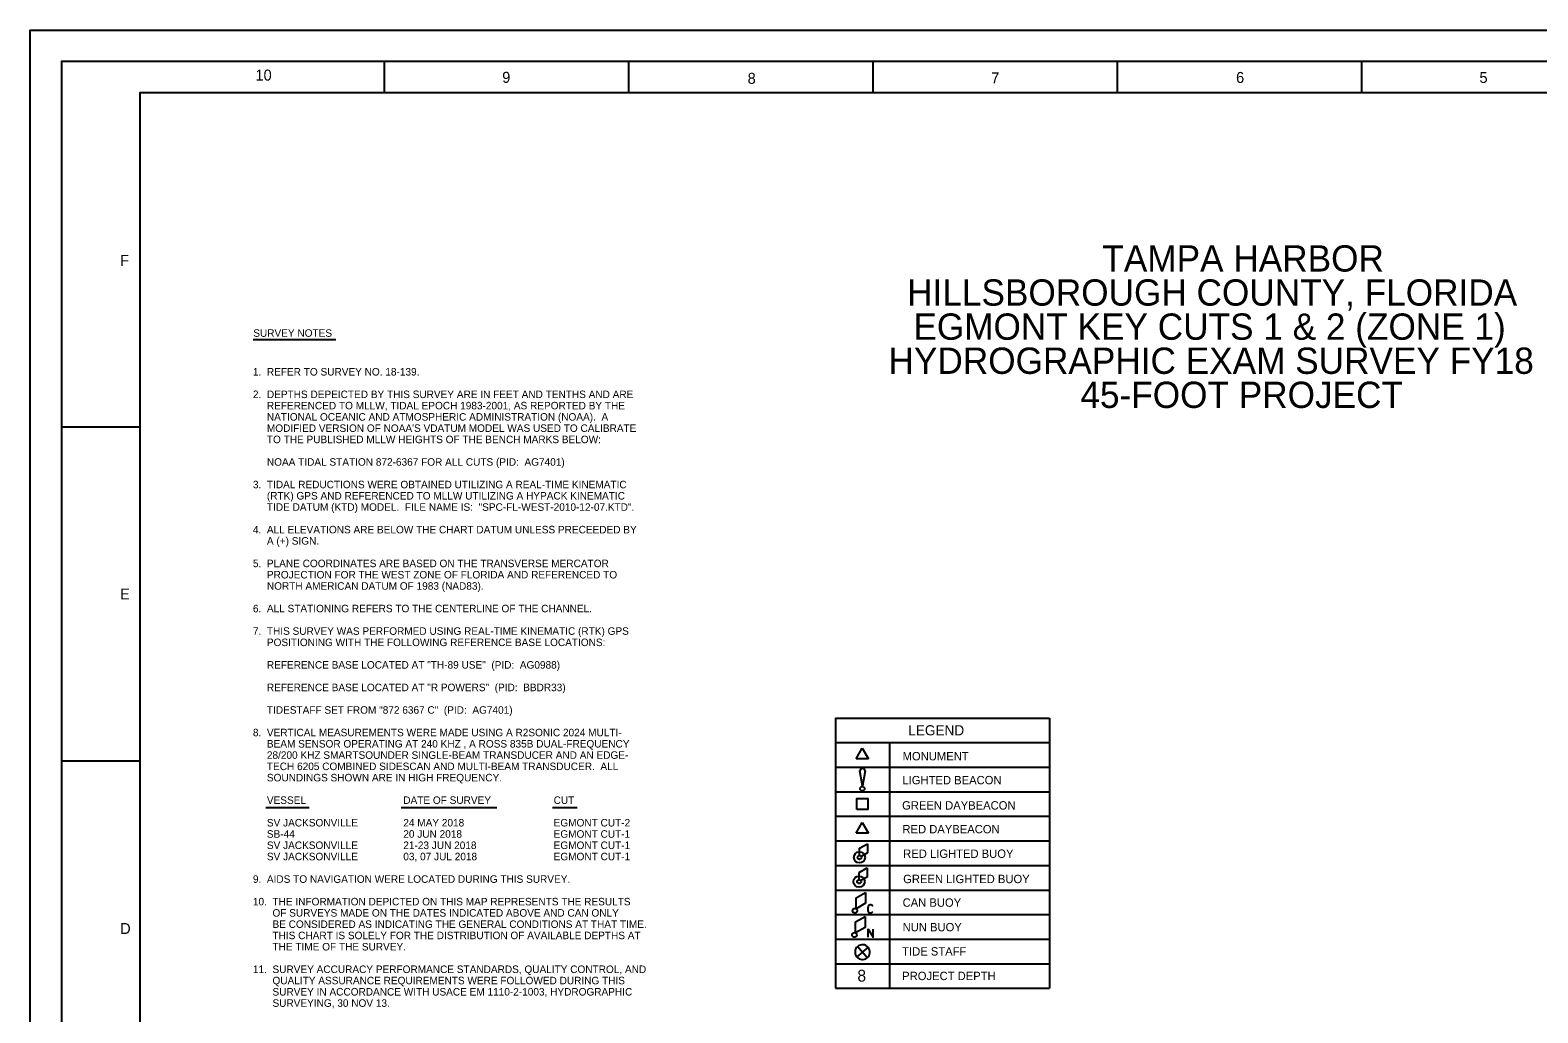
# Model space of a CAD drawing. Extents: x 315926 to 491925, y 1158891 to 1294891.
# Drawn here: x 315926 to 412183, y 1232125 to 1294891 of the extents above; entities that cross this region are included whole.
import ezdxf

# ---------------------------------------------------------------- set-up
doc = ezdxf.new("R2010")
doc.units = 0
for name, color, linetype in [('G-ANNO-NPLT', 7, 'Continuous'), ('G-ANNO-TTLB', 7, 'Continuous'), ('V-ANNO-LEGN', 7, 'Continuous'), ('V-ANNO-TEXT', 7, 'Continuous')]:
    doc.layers.add(name, color=color, linetype=linetype)

msp = doc.modelspace()

# ---------------------------------------------------------------- linework, layer by layer
at = {"layer": 'G-ANNO-NPLT'}
msp.add_lwpolyline([(315926, 1294891), (491925, 1294891), (491925, 1158891), (315926, 1158891)], close=True, dxfattribs=at)
msp.add_lwpolyline([(315926, 1292891), (315926, 1294891), (317926, 1294891)], dxfattribs=at)
at = {"layer": 'G-ANNO-TTLB'}
for p, q in [((338526, 1292891), (338526, 1290891)), ((354126, 1292891), (354126, 1290891)), ((354126, 1292891), (354126, 1290891)), ((369726, 1292891), (369726, 1290891)), ((385326, 1292891), (385326, 1290891)), ((400926, 1292891), (400926, 1290891)), ((317926, 1269551), (322926, 1269551)), ((317926, 1248219), (322926, 1248219))]:
    msp.add_line(p, q, dxfattribs=at)
for points in [[(317926, 1160891), (489925, 1160891), (489925, 1292891), (317926, 1292891)], [(487925, 1290891), (322926, 1290891), (322926, 1162891), (487925, 1162891)]]:
    msp.add_lwpolyline(points, close=True, dxfattribs=at)
at = {"layer": 'V-ANNO-LEGN'}
for p, q in [((367333, 1250952), (367333, 1233696)), ((367333, 1250952), (380999, 1250952)), ((380999, 1250952), (380999, 1233696)), ((367333, 1249383), (380999, 1249383)), ((368655, 1248353), (369055, 1249039)), ((369055, 1249039), (369447, 1248354)), ((370793, 1249376), (370793, 1233696)), ((367333, 1247815), (380999, 1247815)), ((369449, 1248350), (368655, 1248353)), ((369059, 1246625), (368892, 1247574)), ((369226, 1247574), (369059, 1246625)), ((367333, 1246247), (380999, 1246247)), ((367333, 1244678), (380999, 1244678)), ((368655, 1243606), (369055, 1244293)), ((369055, 1244293), (369447, 1243608)), ((367333, 1243109), (380999, 1243109)), ((369449, 1243604), (368655, 1243606)), ((368874, 1242636), (369380, 1242928)), ((369380, 1242928), (369380, 1242344)), ((368874, 1242177), (368874, 1242636)), ((369380, 1242344), (368982, 1242114)), ((367333, 1241540), (380999, 1241540)), ((368850, 1241093), (369356, 1241385)), ((368850, 1240634), (368850, 1241093)), ((369356, 1240801), (368958, 1240571)), ((369356, 1241385), (369356, 1240801)), ((367333, 1239971), (380999, 1239971)), ((368656, 1239473), (369257, 1239821)), ((369257, 1239821), (369258, 1239126)), ((368657, 1238777), (368656, 1239473)), ((369258, 1239126), (368657, 1238777)), ((367333, 1238402), (380999, 1238402)), ((368624, 1237235), (368627, 1237930)), ((368627, 1237930), (369230, 1238275)), ((369230, 1238275), (369228, 1237580)), ((369228, 1237580), (368624, 1237235)), ((367333, 1236834), (380999, 1236834)), ((369062, 1236003), (368697, 1235700)), ((368759, 1236369), (369062, 1236003)), ((369062, 1236003), (369428, 1236307)), ((369366, 1235638), (369062, 1236003)), ((367333, 1235265), (380999, 1235265)), ((367333, 1233696), (380999, 1233696))]:
    msp.add_line(p, q, dxfattribs=at)
msp.add_lwpolyline([(368703, 1245111), (368704, 1245819), (369412, 1245818), (369411, 1245110)], close=True, dxfattribs=at)
for points in [[(369720, 1238916), (369656, 1239000), (369592, 1239016), (369548, 1239016), (369488, 1238999), (369420, 1238916), (369405, 1238804), (369405, 1238744), (369405, 1238704), (369409, 1238668), (369421, 1238604), (369489, 1238524), (369549, 1238509), (369585, 1238509), (369653, 1238525), (369720, 1238605)], [(369431, 1236958), (369433, 1237465), (369746, 1236957), (369749, 1237464)]]:
    msp.add_lwpolyline(points, dxfattribs=at)
for centre, radius in [((369057, 1246444), 143), ((368874, 1242052), 355), ((368874, 1242052), 125), ((368850, 1240509), 355), ((368850, 1240509), 125), ((368585, 1238647), 149), ((368552, 1237104), 149)]:
    msp.add_circle(centre, radius, dxfattribs=at)
for centre, radius, start, end in [((369059, 1247561), 168, 4.64421, 175.35452), ((369062, 1236004), 475, 129.68581, 219.68582), ((369062, 1236004), 475, 39.68564, 129.68577), ((369062, 1236004), 475, 309.6858, 39.68585), ((369062, 1236004), 475, 219.6858, 309.68579)]:
    msp.add_arc(centre, radius, start, end, dxfattribs=at)
at = {"layer": 'V-ANNO-TEXT'}
for p, q in [((330171, 1275132), (335438, 1275132)), ((330981, 1245243), (333745, 1245243)), ((339606, 1245243), (345719, 1245243)), ((349268, 1245243), (350843, 1245243))]:
    msp.add_line(p, q, dxfattribs=at)

# ---------------------------------------------------------------- texts
at = {"layer": 'G-ANNO-TTLB'}
for s, p in [('10', (330309, 1291669)), ('9', (346061, 1291528)), ('8', (361731, 1291462)), ('7', (377279, 1291491)), ('6', (392917, 1291519)), ('5', (408456, 1291518)), ('F', (321668, 1279836)), ('E', (321663, 1258528)), ('D', (321668, 1237161))]:
    msp.add_text(s, height=700, dxfattribs=at).set_placement(p)
at = {"layer": 'V-ANNO-LEGN'}
for s, height, p in [('LEGEND', 649, (371989, 1249849)), ('MONUMENT', 535.4, (371627, 1248251)), ('LIGHTED BEACON', 535.39, (371616, 1246722)), ('GREEN DAYBEACON', 535.39, (371596, 1245108)), ('RED DAYBEACON', 535.39, (371616, 1243590)), ('RED LIGHTED BUOY', 535.39, (371664, 1242023)), ('GREEN LIGHTED BUOY', 535.39, (371664, 1240410)), ('CAN BUOY', 535.4, (371627, 1238902)), ('NUN BUOY', 535.4, (371627, 1237333)), ('TIDE STAFF', 535.4, (371600, 1235783)), ('8', 751, (368738, 1234123)), ('PROJECT DEPTH', 535.39, (371600, 1234217))]:
    msp.add_text(s, height=height, rotation=360, dxfattribs=at).set_placement(p)
at = {"layer": 'V-ANNO-TEXT'}
for s, height, p in [('TAMPA HARBOR', 1680, (384379, 1279471)), ('HILLSBOROUGH COUNTY, FLORIDA', 1680, (371917, 1277293)), ('EGMONT KEY CUTS 1 & 2 (ZONE 1)', 1680, (372312, 1275115)), ('SURVEY NOTES', 480, (330171, 1275305)), ('HYDROGRAPHIC EXAM SURVEY FY18', 1680, (370728, 1272937)), ('1.  REFER TO SURVEY NO. 18-139.  ', 480, (330149, 1272830)), ('2.  DEPTHS DEPEICTED BY THIS SURVEY ARE IN FEET AND TENTHS AND ARE', 480, (330149, 1271390)), ('45-FOOT PROJECT', 1680, (382976, 1270759)), ('     REFERENCED TO MLLW, TIDAL EPOCH 1983-2001, AS REPORTED BY THE', 480, (330149, 1270670)), ('     NATIONAL OCEANIC AND ATMOSPHERIC ADMINISTRATION (NOAA).  A', 480, (330149, 1269950)), ("     MODIFIED VERSION OF NOAA'S VDATUM MODEL WAS USED TO CALIBRATE", 480, (330149, 1269230)), ('     TO THE PUBLISHED MLLW HEIGHTS OF THE BENCH MARKS BELOW:', 480, (330149, 1268510)), ('     NOAA TIDAL STATION 872-6367 FOR ALL CUTS (PID:  AG7401)', 480, (330149, 1267070)), ('3.  TIDAL REDUCTIONS WERE OBTAINED UTILIZING A REAL-TIME KINEMATIC', 480, (330149, 1265630)), ('     (RTK) GPS AND REFERENCED TO MLLW UTILIZING A HYPACK KINEMATIC', 480, (330149, 1264910)), ('     TIDE DATUM (KTD) MODEL.  FILE NAME IS:  "SPC-FL-WEST-2010-12-07.KTD".', 480, (330149, 1264190)), ('4.  ALL ELEVATIONS ARE BELOW THE CHART DATUM UNLESS PRECEEDED BY', 480, (330149, 1262750)), ('     A (+) SIGN.', 480, (330149, 1262030)), ('5.  PLANE COORDINATES ARE BASED ON THE TRANSVERSE MERCATOR', 480, (330149, 1260590)), ('     PROJECTION FOR THE WEST ZONE OF FLORIDA AND REFERENCED TO', 480, (330149, 1259870)), ('     NORTH AMERICAN DATUM OF 1983 (NAD83).', 480, (330149, 1259150)), ('6.  ALL STATIONING REFERS TO THE CENTERLINE OF THE CHANNEL.', 480, (330149, 1257710)), ('7.  THIS SURVEY WAS PERFORMED USING REAL-TIME KINEMATIC (RTK) GPS', 480, (330149, 1256270)), ('     POSITIONING WITH THE FOLLOWING REFERENCE BASE LOCATIONS:', 480, (330149, 1255550)), ('     REFERENCE BASE LOCATED AT "TH-89 USE"  (PID:  AG0988)', 480, (330149, 1254110)), ('     REFERENCE BASE LOCATED AT "R POWERS"  (PID:  BBDR33)', 480, (330149, 1252670)), ('     TIDESTAFF SET FROM "872 6367 C"  (PID:  AG7401) ', 480, (330149, 1251230)), ('8.  VERTICAL MEASUREMENTS WERE MADE USING A R2SONIC 2024 MULTI-', 480, (330149, 1249790)), ('     BEAM SENSOR OPERATING AT 240 KHZ , A ROSS 835B DUAL-FREQUENCY', 480, (330149, 1249070)), ('     28/200 KHZ SMARTSOUNDER SINGLE-BEAM TRANSDUCER AND AN EDGE-', 480, (330149, 1248350)), ('     TECH 6205 COMBINED SIDESCAN AND MULTI-BEAM TRANSDUCER.  ALL', 480, (330149, 1247630)), ('     SOUNDINGS SHOWN ARE IN HIGH FREQUENCY.', 480, (330149, 1246910)), ('     VESSEL', 480, (330149, 1245470)), ('DATE OF SURVEY', 480, (339749, 1245470)), ('CUT', 480, (349349, 1245470)), ('     SV JACKSONVILLE', 480, (330149, 1244030)), ('     SB-44', 480, (330149, 1243310)), ('24 MAY 2018', 480, (339749, 1244030)), ('20 JUN 2018', 480, (339749, 1243310)), ('EGMONT CUT-2', 480, (349349, 1244030)), ('EGMONT CUT-1', 480, (349349, 1243310)), ('     SV JACKSONVILLE', 480, (330149, 1242590)), ('21-23 JUN 2018', 480, (339749, 1242590)), ('EGMONT CUT-1', 480, (349349, 1242590)), ('     SV JACKSONVILLE', 480, (330149, 1241870)), ('03, 07 JUL 2018', 480, (339749, 1241870)), ('EGMONT CUT-1', 480, (349349, 1241870)), ('9.  AIDS TO NAVIGATION WERE LOCATED DURING THIS SURVEY.', 480, (330149, 1240430)), ('10.  THE INFORMATION DEPICTED ON THIS MAP REPRESENTS THE RESULTS', 480, (330149, 1238990)), ('       OF SURVEYS MADE ON THE DATES INDICATED ABOVE AND CAN ONLY', 480, (330149, 1238270)), ('       BE CONSIDERED AS INDICATING THE GENERAL CONDITIONS AT THAT TIME.', 480, (330149, 1237550)), ('       THIS CHART IS SOLELY FOR THE DISTRIBUTION OF AVAILABLE DEPTHS AT', 480, (330149, 1236830)), ('       THE TIME OF THE SURVEY.', 480, (330149, 1236110)), ('11.  SURVEY ACCURACY PERFORMANCE STANDARDS, QUALITY CONTROL, AND', 480, (330149, 1234670)), ('       QUALITY ASSURANCE REQUIREMENTS WERE FOLLOWED DURING THIS', 480, (330149, 1233950)), ('       SURVEY IN ACCORDANCE WITH USACE EM 1110-2-1003, HYDROGRAPHIC', 480, (330149, 1233230)), ('       SURVEYING, 30 NOV 13.    ', 480, (330149, 1232510))]:
    msp.add_text(s, height=height, dxfattribs=at).set_placement(p)

doc.saveas('drawing.dxf')
